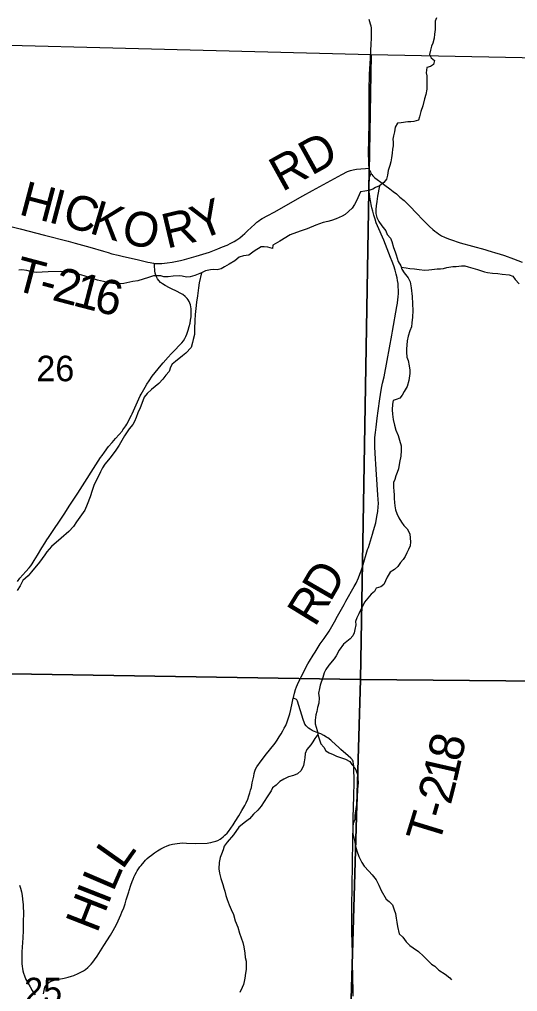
# Model space of a CAD drawing. Extents: x -7.1 to 34, y 0 to 22.
# Drawn here: x 5.098 to 5.914, y 15.224 to 16.818 of the extents above; entities that cross this region are included whole.
import ezdxf

# ---------------------------------------------------------------- set-up
doc = ezdxf.new("R2010")
doc.units = 0
for name, color, linetype in [('GM_X_County_Road', 7, 'Continuous'), ('GM_X_Minor_River', 7, 'Continuous'), ('GM_X_Section', 7, 'Continuous'), ('GM_X_Section_Text', 7, 'Continuous'), ('GM_X_Township_Road', 7, 'Continuous'), ('GM_X_Township_Road_Text', 7, 'Continuous')]:
    doc.layers.add(name, color=color, linetype=linetype)

msp = doc.modelspace()

# ---------------------------------------------------------------- linework, layer by layer
at = {"layer": 'GM_X_County_Road'}
for points in [[(5.6703, 16.8186), (5.6717, 16.8147), (5.6728, 16.8112), (5.6736, 16.8075), (5.6741, 16.804), (5.6744, 16.7998), (5.6745, 16.7942), (5.6742, 16.7871), (5.6739, 16.7781), (5.6727, 16.7544), (5.6712, 16.7281), (5.6707, 16.7024), (5.6705, 16.6839), (5.6702, 16.6506), (5.6698, 16.6196), (5.6695, 16.6009), (5.6698, 16.5832), (5.67, 16.5787), (5.6703, 16.5755), (5.6705, 16.5743), (5.6709, 16.5727), (5.6717, 16.5704), (5.673, 16.5676), (5.6743, 16.5655), (5.6749, 16.5647), (5.6756, 16.5637), (5.6771, 16.5619), (5.6781, 16.5607), (5.6804, 16.5586), (5.684, 16.5556), (5.69, 16.5511), (5.6965, 16.5466), (5.7049, 16.5404), (5.7103, 16.5361), (5.7158, 16.532), (5.7215, 16.527), (5.7281, 16.5213), (5.7375, 16.512), (5.7486, 16.5004), (5.759, 16.4894), (5.7656, 16.4829), (5.7697, 16.4788), (5.7755, 16.4736), (5.7785, 16.4709), (5.7817, 16.4686), (5.7849, 16.4664), (5.7895, 16.4636), (5.7946, 16.4611), (5.8009, 16.4584), (5.809, 16.4555), (5.8153, 16.4535), (5.8204, 16.452), (5.8606, 16.4409), (5.8658, 16.4394), (5.8712, 16.4378), (5.8783, 16.4356), (5.8843, 16.4336), (5.8926, 16.4309), (5.9074, 16.4257), (5.9221, 16.4204)], [(5.0976, 15.3986), (5.0991, 15.3937), (5.1008, 15.3877), (5.1019, 15.3816), (5.1028, 15.3755), (5.1037, 15.3661), (5.104, 15.3507), (5.1038, 15.3407), (5.1036, 15.3242), (5.1031, 15.3121), (5.1018, 15.2893), (5.1014, 15.2765), (5.1015, 15.2702), (5.1019, 15.2655), (5.1024, 15.2622), (5.1032, 15.2583), (5.1042, 15.2544), (5.1059, 15.2498), (5.1083, 15.2442), (5.1116, 15.2382), (5.1153, 15.2318), (5.1186, 15.2261), (5.1233, 15.2186)]]:
    msp.add_lwpolyline(points, dxfattribs=at)
at = {"layer": 'GM_X_Minor_River'}
for points in [[(5.7814, 16.821), (5.7792, 16.8152), (5.7793, 16.8103), (5.779, 16.8015), (5.778, 16.7939), (5.7773, 16.7874), (5.7755, 16.7794), (5.7733, 16.7744), (5.7715, 16.7679), (5.7697, 16.7606), (5.7728, 16.7554), (5.7782, 16.7509), (5.7764, 16.7444), (5.7715, 16.7412), (5.7655, 16.7393), (5.7645, 16.7305), (5.7657, 16.7256), (5.7655, 16.716), (5.7656, 16.7038), (5.7639, 16.6951), (5.7617, 16.6882), (5.7588, 16.6767), (5.7559, 16.6671), (5.7534, 16.6587), (5.7516, 16.653), (5.7441, 16.6506), (5.7391, 16.6505), (5.7342, 16.6501), (5.7237, 16.6488), (5.7176, 16.6479), (5.7135, 16.6414), (5.7125, 16.6341), (5.7111, 16.6273), (5.71, 16.6219), (5.7105, 16.617), (5.7102, 16.6109), (5.7095, 16.6052), (5.7088, 16.5991), (5.7078, 16.591), (5.7064, 16.5845), (5.7046, 16.5788), (5.7021, 16.5704), (5.701, 16.5628), (5.6996, 16.5563), (5.6948, 16.5509), (5.688, 16.5454), (5.6816, 16.5427), (5.6768, 16.5399), (5.6704, 16.5379), (5.6639, 16.5367), (5.6568, 16.5355), (5.6546, 16.5305), (5.6502, 16.5209), (5.6472, 16.5148), (5.6431, 16.5086), (5.6316, 16.4981), (5.6267, 16.4954), (5.6169, 16.4911), (5.609, 16.4887), (5.6033, 16.4867), (5.5954, 16.485), (5.5837, 16.4807), (5.5694, 16.4748), (5.5581, 16.4708), (5.5415, 16.4648), (5.5247, 16.4547), (5.513, 16.448), (5.5123, 16.4427), (5.5047, 16.4445), (5.4987, 16.4452), (5.4938, 16.4451), (5.4825, 16.4381), (5.4739, 16.4318), (5.4648, 16.4306), (5.4576, 16.4286), (5.4505, 16.4224), (5.4415, 16.4169), (5.434, 16.4126), (5.4284, 16.4095), (5.422, 16.4078), (5.4159, 16.4081), (5.4106, 16.4077), (5.4027, 16.4057), (5.3959, 16.4029), (5.3854, 16.3985), (5.3775, 16.3961), (5.3714, 16.3957), (5.3642, 16.3971), (5.3593, 16.3978), (5.3494, 16.3972), (5.3415, 16.396), (5.3343, 16.3963), (5.3294, 16.3977), (5.3237, 16.398), (5.3173, 16.3975), (5.3093, 16.3951), (5.2916, 16.3895)], [(5.688, 16.5454), (5.6849, 16.5283), (5.6835, 16.5199), (5.6825, 16.5126), (5.6818, 16.5065), (5.6819, 16.4997), (5.6835, 16.4936), (5.6866, 16.4868), (5.692, 16.4796), (5.6982, 16.4717), (5.7005, 16.4657), (5.7059, 16.4597), (5.7083, 16.454), (5.7107, 16.4441), (5.7135, 16.4373), (5.7154, 16.432), (5.7186, 16.4214), (5.7229, 16.4142), (5.7248, 16.4089), (5.7283, 16.4025), (5.7349, 16.3946), (5.7384, 16.3878), (5.7401, 16.3779), (5.7414, 16.3639), (5.7419, 16.3521), (5.7425, 16.341), (5.7419, 16.33), (5.7409, 16.3205), (5.7402, 16.314), (5.7377, 16.3075), (5.7351, 16.2987), (5.7334, 16.2914), (5.7327, 16.2838), (5.732, 16.2781), (5.7321, 16.2724), (5.733, 16.2644), (5.735, 16.2591), (5.7366, 16.2503), (5.7375, 16.2431), (5.7375, 16.2374), (5.7362, 16.2264), (5.7333, 16.2164), (5.7285, 16.208), (5.7252, 16.2022), (5.7215, 16.1972), (5.7151, 16.1952), (5.7102, 16.1936), (5.7095, 16.1871), (5.7089, 16.178), (5.7094, 16.1708), (5.7106, 16.1624), (5.7126, 16.1529), (5.7147, 16.1446), (5.7186, 16.1362), (5.7206, 16.1283), (5.7234, 16.1188), (5.7235, 16.1116), (5.7228, 16.1021), (5.7207, 16.0917), (5.719, 16.0814), (5.7168, 16.0753), (5.7146, 16.0699), (5.7128, 16.0638), (5.711, 16.0589), (5.7107, 16.0512), (5.7112, 16.0444), (5.712, 16.0387), (5.7121, 16.0326), (5.7126, 16.0261), (5.713, 16.0208), (5.7143, 16.014), (5.7166, 16.0079), (5.7198, 16.0011), (5.724, 15.9936), (5.7279, 15.9883), (5.7333, 15.9827), (5.7376, 15.9747), (5.7384, 15.9675), (5.7389, 15.9614), (5.7382, 15.9553), (5.7353, 15.9492), (5.7327, 15.9435), (5.7298, 15.9377), (5.7268, 15.9327), (5.7224, 15.9277), (5.7179, 15.9212), (5.7123, 15.9161), (5.7055, 15.9118), (5.7004, 15.9038), (5.6978, 15.8976), (5.6949, 15.8919), (5.69, 15.888), (5.6825, 15.8856), (5.6795, 15.8802), (5.6743, 15.8756), (5.6687, 15.8694), (5.6635, 15.8629), (5.6543, 15.8437), (5.6506, 15.8368), (5.6488, 15.8307), (5.6489, 15.8257)], [(5.3959, 16.4029), (5.392, 16.3865), (5.391, 16.3781), (5.3893, 16.3651), (5.3879, 16.3548), (5.3869, 16.3441), (5.3859, 16.3346), (5.3853, 16.3247), (5.3848, 16.311), (5.3845, 16.3018), (5.3827, 16.2934), (5.3813, 16.2885), (5.3792, 16.2804), (5.3702, 16.2708), (5.365, 16.2665), (5.3534, 16.2572), (5.3481, 16.2529), (5.3455, 16.2479), (5.343, 16.2411), (5.3378, 16.2349), (5.3326, 16.2283), (5.3262, 16.2214), (5.3143, 16.2113), (5.3068, 16.2047), (5.3023, 16.1986), (5.2983, 16.1882), (5.2954, 16.1813), (5.2917, 16.1729), (5.2888, 16.1653), (5.2863, 16.1591), (5.2833, 16.1541), (5.2777, 16.1468), (5.2696, 16.1353), (5.2655, 16.128), (5.2611, 16.1203), (5.2559, 16.1119), (5.2462, 16.0995), (5.2377, 16.0891), (5.234, 16.083), (5.2307, 16.0761), (5.2196, 16.0542), (5.2167, 16.0458), (5.2135, 16.0355), (5.2087, 16.0228), (5.2047, 16.0136), (5.1914, 15.9944), (5.1862, 15.9867), (5.1787, 15.9786), (5.166, 15.9678), (5.1503, 15.9542), (5.1425, 15.9453), (5.1391, 15.94), (5.1306, 15.928), (5.1176, 15.9126), (5.112, 15.9061), (5.1034, 15.8983), (5.0986, 15.8895), (5.0938, 15.8818)], [(5.2916, 16.3895), (5.2837, 16.3883), (5.269, 16.3854), (5.2622, 16.3845), (5.2546, 16.3844), (5.247, 16.3858), (5.2352, 16.3883), (5.2254, 16.3908), (5.2136, 16.3945), (5.2037, 16.3977), (5.1923, 16.401), (5.1794, 16.4035), (5.1653, 16.4048), (5.1449, 16.4041), (5.1351, 16.4036), (5.1252, 16.4034), (5.1157, 16.4048), (5.11, 16.4066), (5.1013, 16.4076), (5.0964, 16.4068)], [(5.7237, 16.4121), (5.7316, 16.4109), (5.7377, 16.4099), (5.7453, 16.4092), (5.7532, 16.4082), (5.762, 16.4072), (5.7688, 16.4077), (5.7737, 16.4081), (5.7824, 16.4094), (5.7881, 16.4095), (5.793, 16.4099), (5.7983, 16.4112), (5.8081, 16.4128), (5.8134, 16.4133), (5.8221, 16.4142), (5.8281, 16.4143), (5.8334, 16.4125), (5.8487, 16.4081), (5.8601, 16.4045), (5.865, 16.4034), (5.8734, 16.402), (5.8817, 16.4018), (5.8889, 16.4007), (5.9006, 16.3994), (5.9064, 16.3972), (5.9106, 16.3919), (5.9171, 16.3848)], [(5.6489, 15.8257), (5.6475, 15.8177), (5.6464, 15.8124), (5.6442, 15.8074), (5.6397, 15.8024), (5.6289, 15.7938), (5.6218, 15.7838), (5.6167, 15.7746), (5.6137, 15.7696), (5.6048, 15.7592), (5.6, 15.7523), (5.5974, 15.7469), (5.5949, 15.7393), (5.5905, 15.7266), (5.5898, 15.7213), (5.588, 15.7133), (5.5889, 15.7057), (5.5883, 15.6969), (5.5865, 15.69), (5.5854, 15.6835), (5.5836, 15.6778), (5.5826, 15.669), (5.5827, 15.663), (5.5855, 15.6523), (5.5872, 15.6436), (5.5919, 15.6304), (5.5965, 15.6247), (5.6, 15.6191), (5.6054, 15.6157), (5.6118, 15.6131), (5.6176, 15.6102), (5.6324, 15.6054), (5.6393, 15.6014), (5.6424, 15.5965), (5.6474, 15.5908), (5.6497, 15.5859), (5.6517, 15.5799), (5.653, 15.5662), (5.652, 15.5555), (5.6511, 15.5422), (5.6512, 15.5368), (5.6494, 15.5277), (5.6477, 15.5128), (5.6475, 15.5063), (5.6445, 15.4998), (5.6442, 15.4949), (5.6444, 15.4827), (5.6468, 15.4717), (5.6488, 15.4626), (5.6505, 15.455), (5.654, 15.4455), (5.6587, 15.4357), (5.663, 15.43), (5.6703, 15.4214), (5.676, 15.4158), (5.6826, 15.4075), (5.6869, 15.3988), (5.6908, 15.3901), (5.699, 15.3758), (5.7039, 15.3717), (5.7093, 15.3664), (5.7121, 15.3584), (5.7144, 15.352), (5.7153, 15.3444), (5.7162, 15.338), (5.7174, 15.3311), (5.7202, 15.319), (5.726, 15.3134), (5.7318, 15.3055), (5.7379, 15.2998), (5.7429, 15.2961), (5.7517, 15.2901), (5.7598, 15.2823), (5.7674, 15.2752), (5.7732, 15.2691), (5.7785, 15.2658), (5.7851, 15.2594), (5.7954, 15.2527), (5.8031, 15.2464), (5.8057, 15.2432)], [(5.5868, 15.6456), (5.5819, 15.639), (5.5786, 15.6336), (5.5753, 15.6286), (5.5689, 15.6209), (5.566, 15.6144), (5.5653, 15.6075), (5.5643, 15.6006), (5.5633, 15.5949), (5.5596, 15.5869), (5.5536, 15.5814), (5.5472, 15.5787), (5.5389, 15.5763), (5.531, 15.5723), (5.5243, 15.5688), (5.5183, 15.5626), (5.5127, 15.5584), (5.5101, 15.5534), (5.5068, 15.5484), (5.5038, 15.5434), (5.499, 15.5357), (5.4938, 15.528), (5.4882, 15.5215), (5.4815, 15.5153), (5.4748, 15.5076), (5.4658, 15.5006), (5.4572, 15.4936), (5.4483, 15.4809), (5.4383, 15.469), (5.4334, 15.4628), (5.4316, 15.4567), (5.4287, 15.4494), (5.4269, 15.4441), (5.4251, 15.436), (5.4245, 15.4254), (5.4258, 15.4182), (5.4278, 15.4094), (5.4313, 15.3996), (5.4329, 15.3939), (5.4341, 15.389), (5.4361, 15.3818), (5.4381, 15.3749), (5.4413, 15.3666), (5.4448, 15.3587), (5.4487, 15.3504), (5.4511, 15.3401), (5.4558, 15.3295), (5.4582, 15.3197), (5.4638, 15.3045), (5.4657, 15.2977), (5.467, 15.2871), (5.4679, 15.2798), (5.4691, 15.2738), (5.4693, 15.2604), (5.4683, 15.2543), (5.4672, 15.2463), (5.4658, 15.2406), (5.4648, 15.2356), (5.4629, 15.2307), (5.4589, 15.2226)]]:
    msp.add_lwpolyline(points, dxfattribs=at)
at = {"layer": 'GM_X_Section'}
for points in [[(4.6565, 16.7868), (5.6742, 16.7607), (5.6569, 15.7356), (4.645, 15.7523)], [(5.6742, 16.7607), (6.6929, 16.7402), (6.6705, 15.7268), (5.6569, 15.7356)], [(5.6569, 15.7356), (5.6272, 14.7254), (4.6234, 14.7351), (4.645, 15.7523)], [(6.6705, 15.7268), (6.6482, 14.7054), (5.6272, 14.7254), (5.6569, 15.7356)]]:
    msp.add_lwpolyline(points, close=True, dxfattribs=at)
at = {"layer": 'GM_X_Township_Road'}
for points in [[(5.0711, 16.4818), (5.0988, 16.4747), (5.1386, 16.4644), (5.1776, 16.4544), (5.1892, 16.4513), (5.2131, 16.4446), (5.2356, 16.438), (5.2432, 16.4358), (5.2492, 16.4341), (5.2596, 16.4314), (5.2661, 16.4299), (5.2734, 16.4282), (5.2904, 16.4243), (5.308, 16.4203), (5.3119, 16.4195), (5.3173, 16.4183), (5.3189, 16.4181), (5.32, 16.4179), (5.3211, 16.4179), (5.331, 16.4181), (5.3397, 16.4188), (5.3479, 16.4201), (5.3616, 16.4229), (5.3684, 16.4245), (5.3796, 16.4276), (5.3875, 16.4298), (5.4091, 16.4368), (5.4173, 16.4398), (5.423, 16.4419), (5.4307, 16.4452), (5.4383, 16.4483), (5.4443, 16.4511), (5.4494, 16.4539), (5.4539, 16.4567), (5.4591, 16.4603), (5.4631, 16.4638), (5.467, 16.4671), (5.4713, 16.4713), (5.4833, 16.4824), (5.487, 16.4856), (5.49, 16.488), (5.4929, 16.4899), (5.4956, 16.4916), (5.5048, 16.4967), (5.5151, 16.5023), (5.5622, 16.5288), (5.5782, 16.5378), (5.626, 16.5637), (5.6356, 16.5686), (5.6403, 16.5704), (5.645, 16.5716), (5.6504, 16.5725), (5.6573, 16.573), (5.6651, 16.5736), (5.6705, 16.5743)], [(5.1369, 15.2206), (5.1379, 15.226), (5.1387, 15.2289), (5.1395, 15.2311), (5.1407, 15.2335), (5.1425, 15.2357), (5.1438, 15.2371), (5.1458, 15.2388), (5.1475, 15.24), (5.1498, 15.2411), (5.1529, 15.2423), (5.1568, 15.2434), (5.1624, 15.2446), (5.1708, 15.2462), (5.1773, 15.2477), (5.1829, 15.2493), (5.1867, 15.2506), (5.1938, 15.2536), (5.1981, 15.2558), (5.2025, 15.2583), (5.2059, 15.2606), (5.2096, 15.2636), (5.2119, 15.2658), (5.215, 15.2691), (5.2178, 15.2724), (5.2208, 15.2764), (5.2249, 15.2823), (5.2303, 15.2907), (5.236, 15.2997), (5.2468, 15.3167), (5.2515, 15.3244), (5.254, 15.329), (5.2571, 15.3353), (5.2638, 15.3497), (5.2657, 15.3541), (5.2685, 15.3614), (5.2708, 15.3682), (5.2727, 15.3744), (5.2767, 15.3876), (5.2775, 15.3899), (5.2802, 15.3985), (5.2824, 15.4048), (5.284, 15.4087), (5.2857, 15.413), (5.2867, 15.415), (5.2894, 15.4201), (5.2906, 15.422), (5.2929, 15.4254), (5.2952, 15.4285), (5.2972, 15.431), (5.302, 15.4367), (5.3045, 15.4395), (5.307, 15.4421), (5.3102, 15.4449), (5.314, 15.448), (5.3191, 15.4517), (5.3238, 15.4548), (5.3294, 15.4581), (5.3347, 15.4608), (5.3398, 15.463), (5.3444, 15.4647), (5.3483, 15.4657), (5.3524, 15.4666), (5.3564, 15.4672), (5.3605, 15.4676), (5.3643, 15.4678), (5.3716, 15.4676), (5.387, 15.4671), (5.4054, 15.4676), (5.4082, 15.4679), (5.4113, 15.4685), (5.4154, 15.4695), (5.4198, 15.4709), (5.4231, 15.4721), (5.4265, 15.4739), (5.4289, 15.4755), (5.4318, 15.4779), (5.4346, 15.4805), (5.438, 15.4841), (5.4402, 15.4867), (5.4479, 15.4974), (5.4515, 15.5029), (5.4572, 15.5123), (5.4624, 15.521), (5.467, 15.5294), (5.4692, 15.5338), (5.472, 15.5399), (5.4739, 15.5449), (5.4756, 15.5499), (5.4767, 15.5543), (5.4778, 15.5587), (5.4793, 15.5666), (5.4817, 15.5776), (5.4825, 15.5816), (5.4837, 15.5854), (5.4849, 15.5887), (5.4869, 15.5927), (5.4893, 15.5964), (5.4911, 15.5989), (5.5007, 15.6115), (5.5167, 15.6315), (5.5201, 15.6364), (5.5237, 15.6418), (5.5267, 15.6467), (5.5296, 15.6516), (5.5319, 15.656), (5.5341, 15.6605), (5.5364, 15.6665), (5.5387, 15.6732), (5.5407, 15.6798), (5.5425, 15.6868), (5.5447, 15.6968), (5.5465, 15.7052), (5.5468, 15.7065), (5.5486, 15.7136), (5.5504, 15.7194), (5.5518, 15.7236), (5.5533, 15.7275), (5.5571, 15.7356), (5.5594, 15.7402), (5.5707, 15.7613), (5.5732, 15.7658), (5.5793, 15.776), (5.5822, 15.7806), (5.5908, 15.7942), (5.5971, 15.8031), (5.6052, 15.8153), (5.6098, 15.8228), (5.6141, 15.8302), (5.6192, 15.8397), (5.6298, 15.8588), (5.6329, 15.8642), (5.6465, 15.8883), (5.6494, 15.8938), (5.6535, 15.9028), (5.6558, 15.9085), (5.6579, 15.9138), (5.6602, 15.9207), (5.6685, 15.9489), (5.6697, 15.9525), (5.6766, 15.9742), (5.6783, 15.98), (5.6817, 15.993), (5.6832, 16), (5.6843, 16.0059), (5.6851, 16.0115), (5.6858, 16.019), (5.6861, 16.0247), (5.6858, 16.0312), (5.6854, 16.0384), (5.6848, 16.0469), (5.6817, 16.0892), (5.6811, 16.0975), (5.6806, 16.1072), (5.6802, 16.1171), (5.6804, 16.1326), (5.6811, 16.1406), (5.6822, 16.1496), (5.684, 16.1643), (5.6855, 16.1766), (5.6884, 16.1958), (5.6896, 16.2034), (5.6914, 16.2136), (5.6931, 16.2216), (5.6954, 16.2324), (5.7004, 16.2589), (5.7082, 16.3003), (5.7094, 16.3072), (5.7165, 16.3476), (5.7173, 16.3529), (5.7181, 16.3588), (5.7184, 16.3629), (5.7189, 16.3692), (5.719, 16.3747), (5.7188, 16.3794), (5.7183, 16.385), (5.7176, 16.3901), (5.7168, 16.3947), (5.7154, 16.4005), (5.7138, 16.4068), (5.7115, 16.4142), (5.7089, 16.4214), (5.7062, 16.428), (5.6948, 16.456), (5.6847, 16.4797), (5.6827, 16.4848), (5.6806, 16.4907), (5.6785, 16.4974), (5.6768, 16.5037), (5.6756, 16.5092), (5.6726, 16.5236), (5.6715, 16.5316), (5.6707, 16.5394), (5.6703, 16.546), (5.6704, 16.5536), (5.671, 16.5565), (5.6717, 16.5595), (5.6726, 16.562), (5.6734, 16.5636), (5.6743, 16.5655)], [(5.0942, 15.8967), (5.0983, 15.9018), (5.1083, 15.9128), (5.1134, 15.9189), (5.1161, 15.9223), (5.1183, 15.9253), (5.122, 15.9309), (5.1274, 15.9398), (5.1343, 15.9515), (5.1391, 15.9592), (5.1425, 15.9647), (5.1451, 15.9687), (5.1719, 16.0088), (5.1793, 16.0201), (5.1932, 16.0415), (5.2305, 16.0996), (5.233, 16.1032), (5.237, 16.1087), (5.2438, 16.1179), (5.2497, 16.1247), (5.2551, 16.131), (5.261, 16.1377), (5.2659, 16.1433), (5.2672, 16.1451), (5.272, 16.152), (5.2735, 16.1547), (5.2811, 16.1692), (5.2823, 16.1716), (5.2958, 16.2009), (5.2973, 16.2039), (5.3036, 16.2151), (5.3067, 16.2202), (5.3103, 16.2257), (5.3154, 16.2331), (5.3299, 16.2514), (5.333, 16.2551), (5.3412, 16.2645), (5.3465, 16.2699), (5.3531, 16.2766), (5.3597, 16.2833), (5.3639, 16.2879), (5.3664, 16.2912), (5.3689, 16.2952), (5.3705, 16.2981), (5.3721, 16.3022), (5.3743, 16.3087), (5.3761, 16.3147), (5.3773, 16.32), (5.3781, 16.3248), (5.3789, 16.3305), (5.3792, 16.3351), (5.3793, 16.3396), (5.3791, 16.3436), (5.3786, 16.3467), (5.3779, 16.3501), (5.3771, 16.353), (5.3757, 16.3559), (5.3744, 16.3583), (5.3725, 16.3608), (5.3692, 16.3641), (5.3654, 16.3669), (5.3643, 16.3676), (5.3613, 16.3694), (5.3561, 16.372), (5.3458, 16.3769), (5.3435, 16.3781), (5.3364, 16.3818), (5.332, 16.3844), (5.3287, 16.387), (5.326, 16.3899), (5.3238, 16.3931), (5.3217, 16.397), (5.3204, 16.402), (5.3197, 16.4059), (5.3194, 16.4086), (5.3192, 16.4117), (5.319, 16.4148), (5.3189, 16.4181)], [(5.6447, 15.2165), (5.6446, 15.2272), (5.6444, 15.2453), (5.6443, 15.2488), (5.6442, 15.254), (5.6441, 15.2573), (5.6439, 15.2619), (5.6438, 15.2666), (5.6436, 15.2729), (5.6434, 15.2814), (5.6434, 15.2921), (5.6433, 15.3003), (5.6427, 15.3261), (5.6424, 15.3469), (5.6426, 15.3659), (5.6428, 15.3753), (5.643, 15.3849), (5.6431, 15.3898), (5.6432, 15.3979), (5.6436, 15.4319), (5.6437, 15.44), (5.6442, 15.4665), (5.6443, 15.4758), (5.6446, 15.4932), (5.6448, 15.5092), (5.6456, 15.5447), (5.6463, 15.5674), (5.6461, 15.5933), (5.646, 15.5945), (5.645, 15.6007), (5.6447, 15.6019), (5.6438, 15.6036), (5.6431, 15.6047), (5.641, 15.6068), (5.6367, 15.6105), (5.6244, 15.6213), (5.6217, 15.6239), (5.6095, 15.6353), (5.608, 15.6366), (5.6034, 15.6401), (5.6012, 15.6414), (5.5967, 15.644), (5.5917, 15.6465), (5.5855, 15.6491), (5.5799, 15.6514), (5.5776, 15.6525), (5.5741, 15.6545), (5.5717, 15.6562), (5.5689, 15.6586), (5.5675, 15.66), (5.5655, 15.6627), (5.5649, 15.664), (5.5629, 15.6703), (5.5536, 15.7003), (5.5531, 15.7015), (5.5524, 15.7025), (5.5518, 15.7031), (5.5507, 15.7037), (5.5478, 15.7047), (5.5465, 15.7052)]]:
    msp.add_lwpolyline(points, dxfattribs=at)

# ---------------------------------------------------------------- texts
at = {"layer": 'GM_X_Section_Text'}
for s, p in [('26', (5.1253, 16.2249)), ('25', (5.1053, 15.2049))]:
    msp.add_text(s, height=0.04186, rotation=0, dxfattribs=at).set_placement(p)
at = {"layer": 'GM_X_Township_Road_Text'}
for s, height, rotation, p in [('RD', 0.05682, 29.0129, (5.5284, 16.5348)), ('H', 0.0568, 345.2561, (5.0948, 16.4989)), ('I', 0.0568, 345.2405, (5.1431, 16.4862)), ('C', 0.0568, 344.7918, (5.1656, 16.4803)), ('K', 0.0568, 343.3751, (5.2103, 16.4682)), ('Y', 0.0568, 21.433, (5.3928, 16.4555)), ('O', 0.0568, 347.5106, (5.2625, 16.4527)), ('R', 0.0568, 13.3735, (5.3391, 16.4421)), ('T', 0.0568, 345.1747, (5.0858, 16.3754)), ('2', 0.0568, 345.2642, (5.1493, 16.3586)), ('-', 0.0568, 345.1994, (5.1269, 16.3645)), ('1', 0.0568, 345.4929, (5.1831, 16.3497)), ('6', 0.0568, 346.0803, (5.2173, 16.3409)), ('D', 0.0568, 60.0324, (5.6073, 15.8616)), ('R', 0.0568, 58.4505, (5.582, 15.8204)), ('8', 0.0568, 77.7505, (5.8216, 15.5993)), ('1', 0.0568, 77.1601, (5.8137, 15.5645)), ('2', 0.0568, 75.6437, (5.8046, 15.529)), ('-', 0.0568, 74.1568, (5.7978, 15.505)), ('T', 0.0568, 72.9366, (5.785, 15.4631)), ('L', 0.0568, 54.7134, (5.2665, 15.4227)), ('L', 0.0568, 66.766, (5.2513, 15.3864)), ('I', 0.0568, 68.5421, (5.243, 15.3651)), ('H', 0.0568, 68.6471, (5.2248, 15.3185))]:
    msp.add_text(s, height=height, rotation=rotation, dxfattribs=at).set_placement(p)

doc.saveas('drawing.dxf')
